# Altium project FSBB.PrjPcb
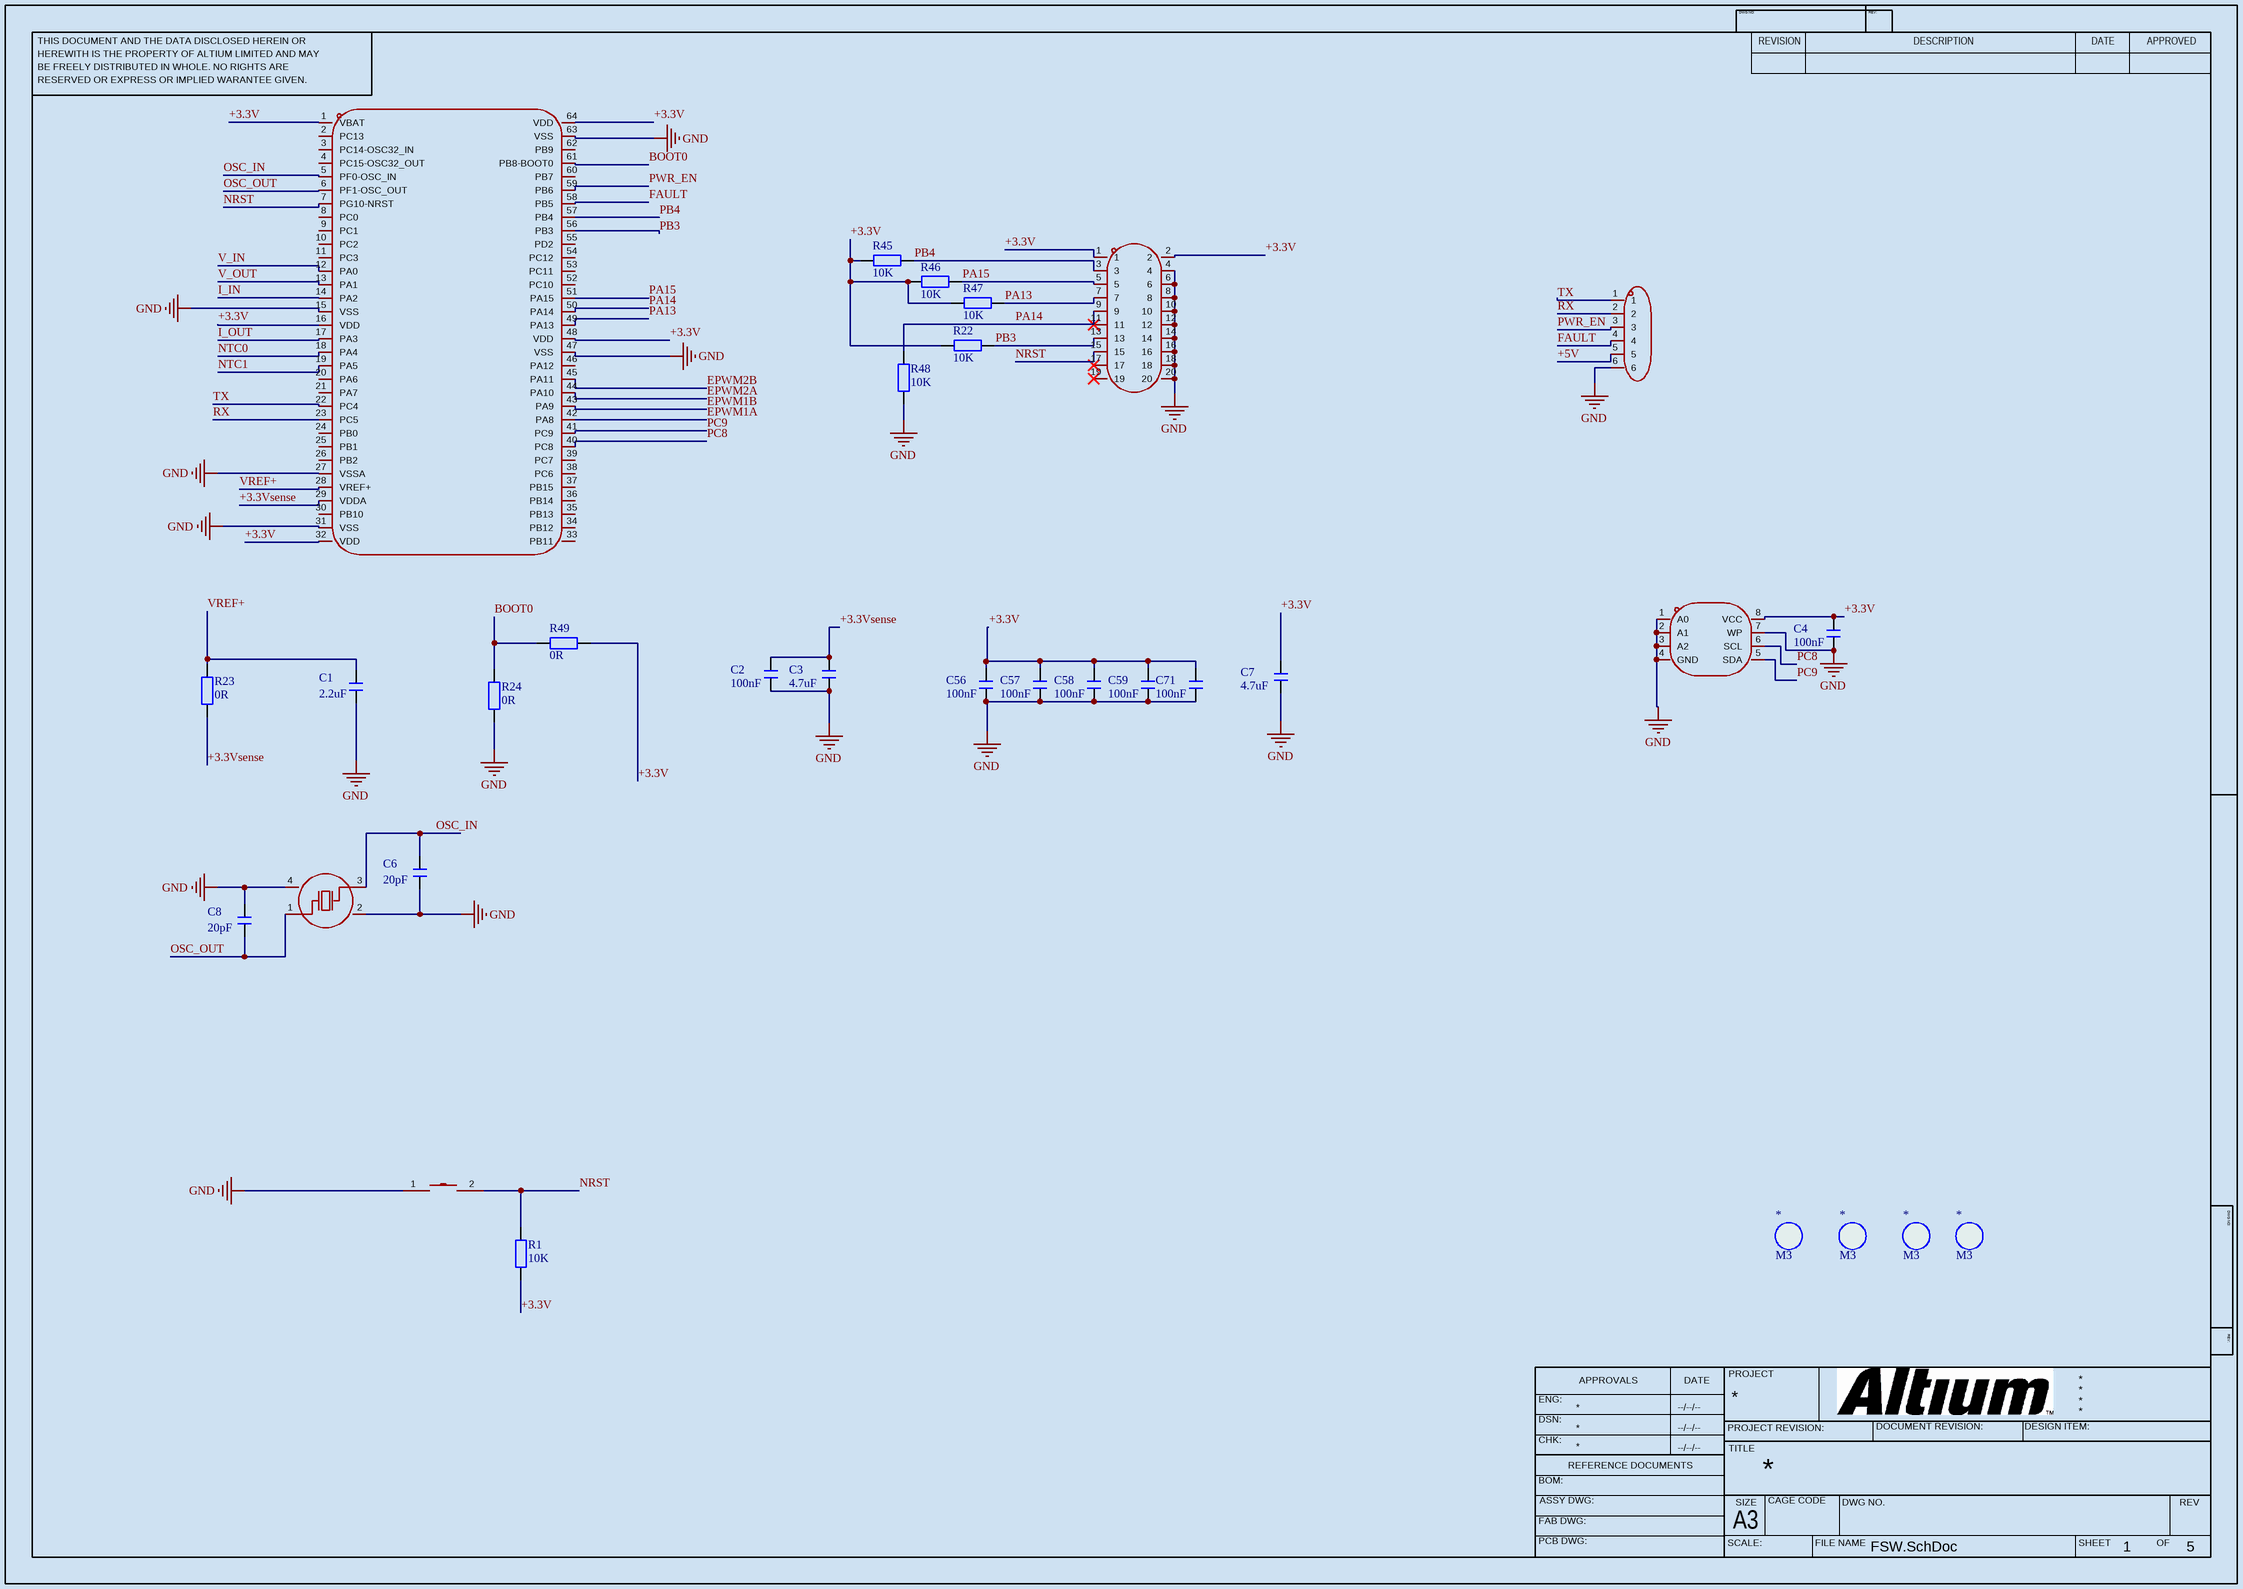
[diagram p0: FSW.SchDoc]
5 sheets, 152 parts. Net scope: global (net labels, ports and power ports of the same name join across sheets).
Board file: FSW.PcbDoc
Sheets:
  FSW.SchDoc
  power.SchDoc
  auxiliary power supply.SchDoc
  sense.SchDoc
  NTC.SchDoc

## Sheet FSW.SchDoc
size 420 x 297 mm; SheetNumber: 1; SheetTotal: 5; ENG_APP_DATE: --/--/--; DSN_APP_DATE: --/--/--; CHK_APP_DATE: --/--/--

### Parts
(Parts that share a designator on the sheet are numbered #1, #2 ... from top to bottom, then left to right.)
*#1  M3  [M3 125X200]
*#2  M3  [M3 125X200]
*#3  M3  [M3 125X200]
*#4  M3  [M3 125X200]
C1  2.2uF  [C 0603_L]
C2  100nF  [C 0603_L]
C3  4.7uF  [C 0603_L]
C4  100nF  [C 0603_L]
C6  20pF  [C 0603_L]
C7  4.7uF  [C 0603_L]
C8  20pF  [C 0603_L]
C56  100nF  [C 0603_L]
C57  100nF  [C 0603_L]
C58  100nF  [C 0603_L]
C59  100nF  [C 0603_L]
C71  100nF  [C 0603_L]
CN1  bh254v-20p  [CONN-TH_20P-P2.54_BH254V-20P]  (value not drawn)
R1  10K  [R 0603_L]
R22  10K  [R 0603_L]
R23  0R  [R 0603_L]
R24  0R  [R 0603_L]
R45  10K  [R 0603_L]
R46  10K  [R 0603_L]
R47  10K  [R 0603_L]
R48  10K  [R 0603_L]
R49  0R  [R 0603_L]
SW1  ts-1101-c-w  [SW-SMD_L6.0-W3.3-LS8.0_TS-1101-C-W]  (value not drawn)
U1  zx-xh2.54-6pzz  [CONN-TH_6P-P2.50_ZX-XH2.54-6PZZ]  (value not drawn)
U14  stm32g474rbt3  [LQFP-64_L10.0-W10.0-P0.50-LS12.0-BL]  (value not drawn)
U15  at24c512c-sshd-t  [SOIC-8_L4.9-W3.9-P1.27-LS6.0-BL]  (value not drawn)
X1  x252024mob4si  [CRYSTAL-SMD_4P-L2.5-W2.0-BL]  (value not drawn)

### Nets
GND: C1.1 C2.1 C3.1 C4.1 C6.1 C7.1 C8.2 C56.1 C57.1 C58.1 C59.1 C71.1 CN1.4 CN1.6 CN1.8 CN1.10 CN1.12 CN1.14 CN1.16 CN1.18 CN1.20 R24.1 R48.2 SW1.1 U1.6 U14.15(VSS) U14.27(VSSA) U14.31(VSS) U14.47(VSS) U14.63(VSS) U15.1(A0) U15.2(A1) U15.3(A2) U15.4(GND) U15.7(WP) X1.2(GND) X1.4(GND)
+3.3V: C4.2 C7.2 C56.2 C57.2 C58.2 C59.2 C71.2 CN1.1 CN1.2 R1.1 R22.2 R45.2 R46.2 R47.2 R49.1 U14.1(VBAT) U14.16(VDD) U14.32(VDD) U14.48(VDD) U14.64(VDD) U15.8(VCC)
+3.3Vsense: C2.2 C3.2 R23.1 U14.29(VDDA)
+5V: U1.5
BOOT0: R24.2 R49.2 U14.61(PB8-BOOT0)
EPWM1A: U14.42(PA8)
EPWM1B: U14.43(PA9)
EPWM2A: U14.44(PA10)
EPWM2B: U14.45(PA11)
FAULT: U1.4 U14.58(PB5)
I_IN: U14.14(PA2)
I_OUT: U14.17(PA3)
NRST: CN1.15 R1.2 SW1.2 U14.7(PG10-NRST)
NTC0: U14.18(PA4)
NTC1: U14.19(PA5)
OSC_IN: C6.2 U14.5(PF0-OSC_IN) X1.3(OSC2)
OSC_OUT: C8.1 U14.6(PF1-OSC_OUT) X1.1(OSC1)
PA13: CN1.7 R47.1 U14.49(PA13)
PA14: CN1.9 CN1.11 R48.1 U14.50(PA14)
PA15: CN1.5 R46.1 U14.51(PA15)
PB3: CN1.13 R22.1 U14.56(PB3)
PB4: CN1.3 R45.1 U14.57(PB4)
PC8: U14.40(PC8) U15.6(SCL)
PC9: U14.41(PC9) U15.5(SDA)
PWR_EN: U1.3 U14.59(PB6)
RX: U1.2 U14.23(PC5)
TX: U1.1 U14.22(PC4)
V_IN: U14.12(PA0)
V_OUT: U14.13(PA1)
VREF+: C1.2 R23.2 U14.28(VREF+)

Not connected (* = marked no-connect by the designer): CN1 17* 19*; U14 2(PC13) 3(PC14-OSC32_IN) 4(PC15-OSC32_OUT) 8(PC0) 9(PC1) 10(PC2) 11(PC3) 20(PA6) 21(PA7) 24(PB0) 25(PB1) 26(PB2) 30(PB10) 33(PB11) 34(PB12) 35(PB13) 36(PB14) 37(PB15) 38(PC6) 39(PC7) 46(PA12) 52(PC10) 53(PC11) 54(PC12) 55(PD2) 60(PB7) 62(PB9)

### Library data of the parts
*#1-*#4 = M3: 铜柱孔; 版权归属: 源创客
C1 C6 C8 = C: 无极性贴片电容; 版权归属: 源创客; 材质: X7R
C2 C4 C56-C59 C71 = C: 6.3V X7R 0603 100nF; BOM名称: 无极性贴片电容; 版权归属: 源创客
C3 C7 = C: 6.3V X7R 0603 4.7uF; BOM名称: 无极性贴片电容; 版权归属: 源创客
CN1 = bh254v-20p: 连接器类型:简牛座;间距:-;结构:2x10P;额定电流:3A;额定电压:250V;安装方式:直插;行距:2.54mm;排数:2;每排PIN数:10;触头材质:-;触头镀层:-;工作温度:-40℃~+105℃;; Manufacturer: XFCN(兴飞); AddInBom: yes; ModelId: f758914ec7d246748ac341cdbdaac489; ModelTransform: 1299.214,350.0906,0,0,0,0,0,1.968,-127.953; Connector Type: 简牛座; Number of Positions or Pins: 2x10P; Current Rating: 3A; Voltage Rating (Max): 250V; Holder Type: 直插; Row Spacing: 2.54mm; Number of PINs Per Row: 10
R1 R22-R24 R45-R49 = R: 贴片电阻; 版权归属: 源创客
SW1 = ts-1101-c-w: 电路结构:单刀单掷;按钮形状:矩形按钮;作用力:2.6N;安装方式:立贴;开关长度:6mm;开关宽度:3.6mm;开关高度:2.5mm;带支架:不带支架;触点电流:50mA;额定电压:12V;带灯:无;工作寿命:5万次;; Manufacturer: XKB Connection(中国星坤); AddInBom: yes; ModelId: 0fd6340cfb7d45bfbbb5f8576d023f85; ModelTransform: 315.232,145.669,0,0,0,0,0,0,0; Circuit: 单刀单掷; Actuator Style: 矩形按钮; Operating Force: 2.6N; Switch Height: 2.5mm; with Bracket: 不带支架; Contact Current: 50mA; Voltage Rating: 12V; With Lamp: 无; Life: 5万次
U1 = zx-xh2.54-6pzz: 插针结构:1x6P;间距:2.5mm;安装方式:直插;参考系列:XH;总PIN数:6P;排数:1;每排PIN数:6;行距:-;额定电流:3A;触头材质:黄铜;触头镀层:锡;工作温度:-25℃~+85℃;; Manufacturer: Megastar(兆星); AddInBom: yes; ModelId: 69bbd5a736b94698bef26e8b4cdae04d; ModelTransform: 688.975,232.6767,0,0,0,0,0,14.528,-133.858; Pins Structure: 1x6P; Pitch: 2.5mm; Reference Series: XH; Number of PINs Per Row: 6; Current Rating: 3A; Voltage Rating: 250V; Plastic Material: PA66; Flame Retardant Rating: UL94V-0; Z-Height of the Board: 7mm; X-Length of Bottom Edge on Board (Spacing Line): 17.5mm; Y-Width of Bottom Edge on Board: 5.9mm
U14 = stm32g474rbt3: CPU内核:ARM Cortex-M4F;CPU最大主频:170MHz;CPU位数:32 Bit;; Manufacturer: ST(意法半导体); AddInBom: yes; ModelId: cd9de06618c44fcf82654c43a457f83c; ModelName: LQFP-64_L10.0-W10.0-H1.4-LS12.0-P0.50; ModelTransform: 472.441,472.441,0,0,0,0,0,0.465,0; CPU Maximum Speed: 170MHz; Core Size: 32 Bit; Program Storage Size: 128KB; Program Memory Type: FLASH; Number of I/O: 52; ADC (Bit): 12bit; Oscillator Type: 内置; Voltage - Supply: 1.71V~3.6V
U15 = at24c512c-sshd-t: 接口类型:I2C;存储容量:512Kbit;时钟频率(fc):1MHz;; Manufacturer: MICROCHIP(美国微芯); AddInBom: yes; ModelId: e81d2f7d937b4a6ab1dca543ff5d56a4; ModelName: SOIC-8_L4.9-W3.9-H1.7-LS6.0-P1.27; ModelTransform: 192.913,236.22,0,0,0,0,0,0,0; Interface: I2C; Clock Frequency: 1MHz; Write Cycle Time(Tw): 5ms; Data Retention - TDR (Year): 40年; Write Cycle Endurance: 100万次; Voltage - Supply: 2.5V~5.5V
X1 = x252024mob4si: 晶振类型:贴片晶振;频率:24MHz;常温频差:±10ppm;负载电容:12pF;频率稳定度:±20ppm;; Manufacturer: YXC(扬兴晶振); AddInBom: yes; ModelId: d23e0abc26e54c15b6292fd5f43702fa; ModelTransform: 98.425,78.74,0,0,0,0,0,0,0; Value: 24MHz; Normal temperature Frequency Tolerance: ±10ppm; Load Capacitance: 12pF; Frequency Stability: ±20ppm; Equivalent Series Resistance(ESR): 100Ω

## Sheet power.SchDoc
size 420 x 297 mm; SheetNumber: 2; SheetTotal: 5; DSN_APP_DATE: --/--/--; CHK_APP_DATE: --/--/--
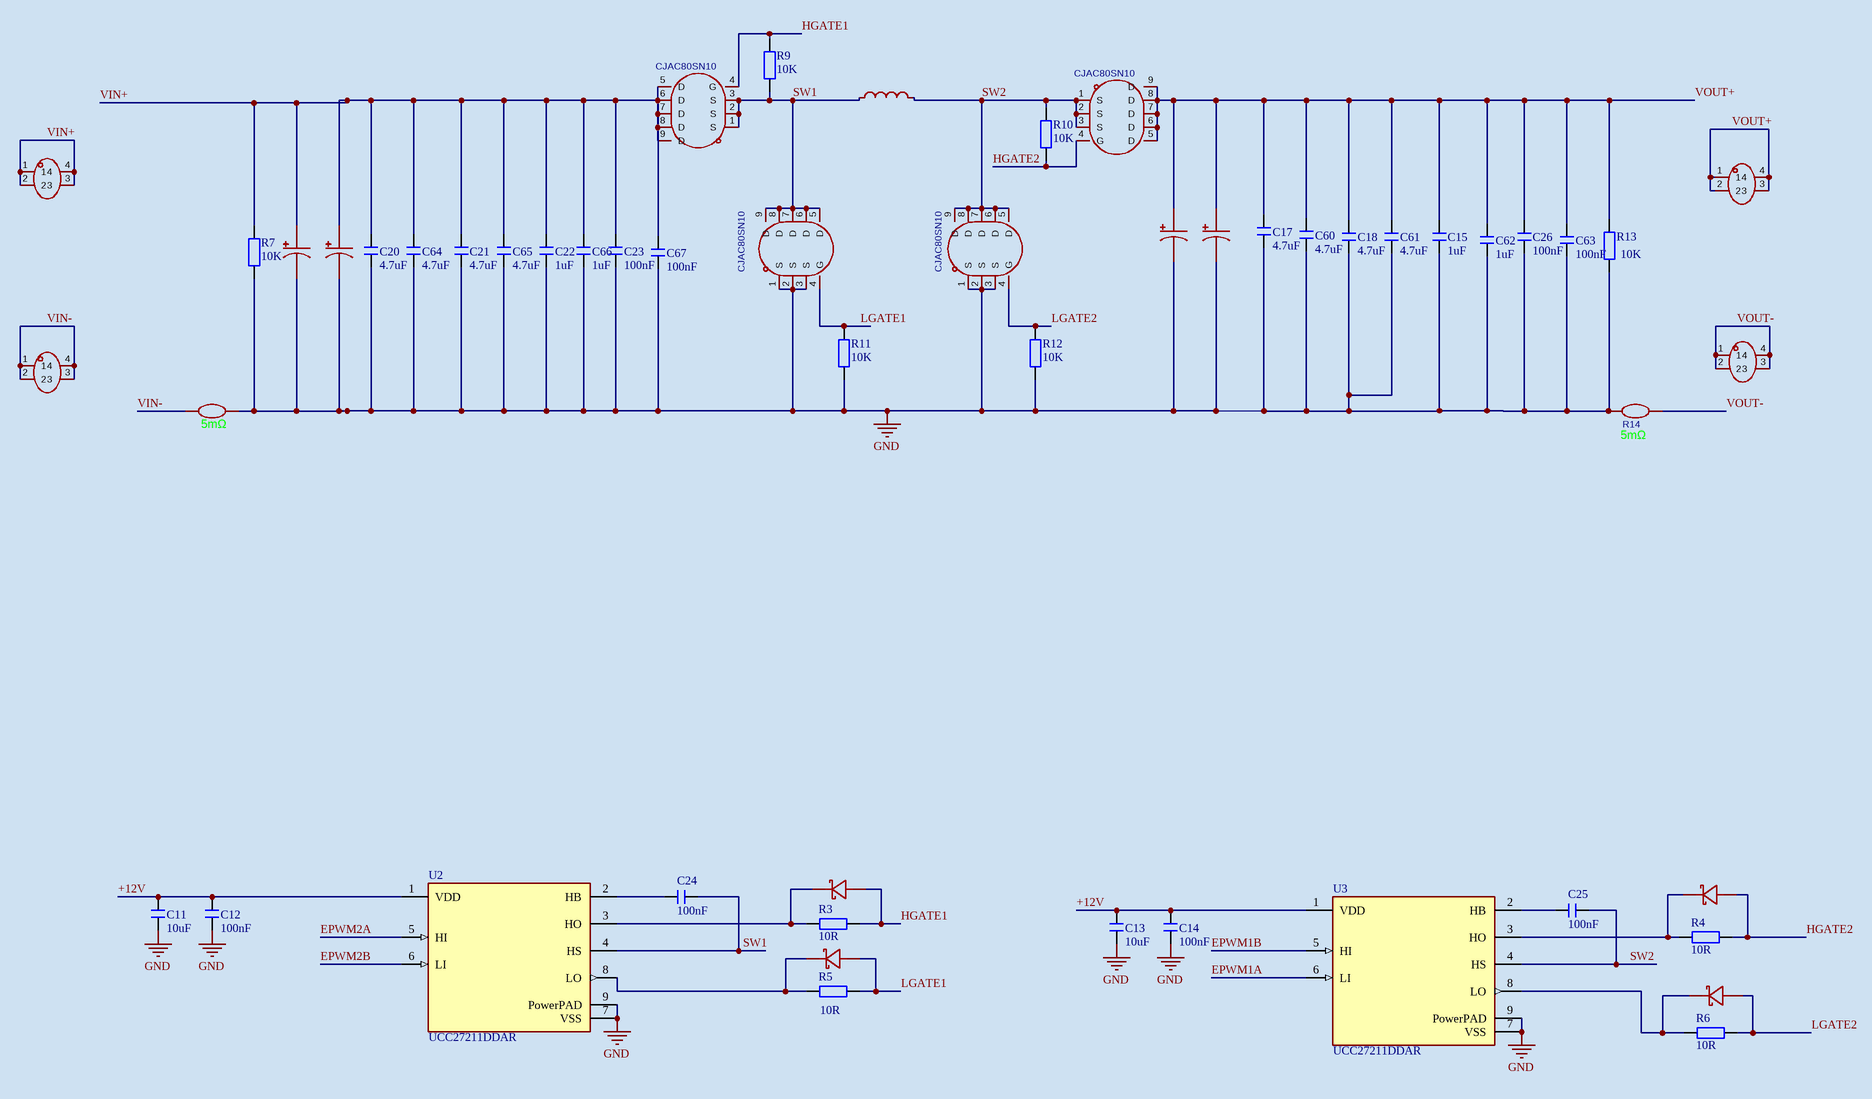
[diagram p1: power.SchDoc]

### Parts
C11  10uF  [C 0805_L]
C12  100nF  [C 0805_L]
C13  10uF  [C 0805_L]
C14  100nF  [C 0805_L]
C15  1uF  [C 1206_L]
C16  100yxj220m12.5x25  [CAP-TH_BD12.5-P5.00-D0.6-FD]  (value not drawn)
C17  4.7uF  [C 1210_L]
C18  4.7uF  [C 1210_L]
C19  100yxj220m12.5x25  [CAP-TH_BD12.5-P5.00-D0.6-FD]  (value not drawn)
C20  4.7uF  [C 1210_L]
C21  4.7uF  [C 1210_L]
C22  1uF  [C 1206_L]
C23  100nF  [C 0805_L]
C24  100nF  [C 0805_L]
C25  100nF  [C 0805_L]
C26  100nF  [C 0805_L]
C53  100yxj220m12.5x25  [CAP-TH_BD12.5-P5.00-D0.6-FD]  (value not drawn)
C54  100yxj220m12.5x25  [CAP-TH_BD12.5-P5.00-D0.6-FD]  (value not drawn)
C60  4.7uF  [C 1210_L]
C61  4.7uF  [C 1210_L]
C62  1uF  [C 1206_L]
C63  100nF  [C 0805_L]
C64  4.7uF  [C 1210_L]
C65  4.7uF  [C 1210_L]
C66  1uF  [C 1206_L]
C67  100nF  [C 0805_L]
D1  1n4148w_c7420318  [SOD-123_L2.7-W1.6-LS3.7-FD]  (value not drawn)
D2  1n4148w_c7420318  [SOD-123_L2.7-W1.6-LS3.7-FD]  (value not drawn)
D3  1n4148w_c7420318  [SOD-123_L2.7-W1.6-LS3.7-FD]  (value not drawn)
D4  1n4148w_c7420318  [SOD-123_L2.7-W1.6-LS3.7-FD]  (value not drawn)
L1  fc-se2822-150m  [IND-TH_L28.0-W23.0_FC-SE2822]  (value not drawn)
Q1  cjac80sn10  [PDFN-8_L5.8-W5.0-P1.27-LS6.0-BL]
Q2  cjac80sn10  [PDFN-8_L5.8-W5.0-P1.27-LS6.0-BL]
Q3  cjac80sn10  [PDFN-8_L5.8-W5.0-P1.27-LS6.0-BL]
Q4  cjac80sn10  [PDFN-8_L5.8-W5.0-P1.27-LS6.0-BL]
R3  10R  [R 0805_L]
R4  10R  [R 0805_L]
R5  10R  [R 0805_L]
R6  10R  [R 0805_L]
R7  10K  [R 1206_L]
R8  value 5mΩ  [RES-SMD_L6.4-W3.2-1]  (hidden comment: hojlr2512-3w-5mr-1%)
R9  10K  [R 0805_L]
R10  10K  [R 0805_L]
R11  10K  [R 0805_L]
R12  10K  [R 0805_L]
R13  10K  [R 1206_L]
R14  value 5mΩ  [RES-SMD_L6.4-W3.2-1]  (hidden comment: hojlr2512-3w-5mr-1%)
U2  UCC27211DDAR  [FP-DDA0008E-IPC_C]
U3  UCC27211DDAR  [FP-DDA0008E-IPC_C]
U10  t34001  [CONN-TH_T34001]  (value not drawn)
U11  t34001  [CONN-TH_T34001]  (value not drawn)
U12  t34001  [CONN-TH_T34001]  (value not drawn)
U13  t34001  [CONN-TH_T34001]  (value not drawn)

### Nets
GND: C11.1 C12.1 C13.1 C14.1 C15.1 C16.2 C17.1 C18.1 C19.2 C20.1 C21.1 C22.1 C23.1 C26.1 C53.2 C54.2 C60.1 C61.1 C62.1 C63.1 C64.1 C65.1 C66.1 C67.1 Q3.1(S) Q3.2(S) Q3.3(S) Q4.1(S) Q4.2(S) Q4.3(S) R7.1 R8.2 R11.1 R12.1 R13.1 R14.1 U2.7(VSS) U2.9(PowerPAD) U3.7(VSS) U3.9(PowerPAD)
+12V: C11.2 C12.2 C13.2 C14.2 U2.1(VDD) U3.1(VDD)
EPWM1A: U3.6(LI)
EPWM1B: U3.5(HI)
EPWM2A: U2.5(HI)
EPWM2B: U2.6(LI)
HGATE1: D1.1(A) Q1.4(G) R3.2 R9.2
HGATE2: D2.1(A) Q2.4(G) R4.2 R10.1
LGATE1: D3.1(A) Q3.4(G) R5.2 R11.2
LGATE2: D4.1(A) Q4.4(G) R6.2 R12.2
SW1: C24.1 L1.1 Q1.1(S) Q1.2(S) Q1.3(S) Q3.5(D) Q3.6(D) Q3.7(D) Q3.8(D) Q3.9(D) R9.1 U2.4(HS)
SW2: C25.1 L1.2 Q2.1(S) Q2.2(S) Q2.3(S) Q4.5(D) Q4.6(D) Q4.7(D) Q4.8(D) Q4.9(D) R10.2 U3.4(HS)
VIN+: C20.2 C21.2 C22.2 C23.2 C53.1 C54.1 C64.2 C65.2 C66.2 C67.2 Q1.5(D) Q1.6(D) Q1.7(D) Q1.8(D) Q1.9(D) R7.2 U10.1 U10.2 U10.3 U10.4
VIN-: R8.1 U13.1 U13.2 U13.3 U13.4
VOUT+: C15.2 C16.1 C17.2 C18.2 C19.1 C26.2 C60.2 C61.2 C62.2 C63.2 Q2.5(D) Q2.6(D) Q2.7(D) Q2.8(D) Q2.9(D) R13.2 U11.1 U11.2 U11.3 U11.4
VOUT-: R14.2 U12.1 U12.2 U12.3 U12.4
NetC24_2: C24.2 U2.2(HB)
NetC25_2: C25.2 U3.2(HB)
NetD1_2: D1.2(K) R3.1 U2.3(HO)
NetD2_2: D2.2(K) R4.1 U3.3(HO)
NetD3_2: D3.2(K) R5.1 U2.8(LO)
NetD4_2: D4.2(K) R6.1 U3.8(LO)

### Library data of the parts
C11 = C: 25V X7R 0805 10uF /; BOM名称: 无极性贴片电容; 版权归属: 源创客
C12 C14 C24 C25 = C: 25V X7R 0805 100nF; BOM名称: 无极性贴片电容; 版权归属: 源创客
C13 = C: 25V X7R 0805 10uF; BOM名称: 无极性贴片电容; 版权归属: 源创客
C15 C62 = C: 100V X7R 1206 1uF; BOM名称: 无极性贴片电容; 版权归属: 源创客
C16 C19 C53 C54 = 100yxj220m12.5x25: 容值:220uF;精度:±20%;额定电压:100V;纹波电流:1.62A@100kHz;等效串联电阻(ESR):-;; Manufacturer: Rubycon(红宝石); AddInBom: yes; ModelId: 968d8ff988964aab8919b46a6a737be2; ModelName: CAP-TH_D12.5-H20.0-P5.00; ModelTransform: 492.5187,492.11201,0,0,0,0,0,0,-137.795; Value: 220uF; Tolerance: ±20%; Voltage Rating: 100V; Pin Spacing: 5mm; Lifetime: 10000hrs@105℃
C17 C18 C60 C61 = C: 100V X7R 1210 4.7uF; BOM名称: 无极性贴片电容; 版权归属: 源创客
C20 C21 C64 C65 = C: 100V X7R 1210  4.7uF; BOM名称: 无极性贴片电容; 版权归属: 源创客
C22 C66 = C: 100V X7R 1206  1uF; BOM名称: 无极性贴片电容; 版权归属: 源创客
C23 = C: 100V X7R 0805 100nF; BOM名称: 无极性贴片电容; 版权归属: 源创客
C26 C63 = C: 100V X7R 0805 100nF /; BOM名称: 无极性贴片电容; 版权归属: 源创客
C67 = C: 100V X7R 0805  100nF /; BOM名称: 无极性贴片电容; 版权归属: 源创客
D1-D4 = 1n4148w_c7420318: 二极管配置:独立式;整流电流:150mA;直流反向耐压(Vr):100V;正向压降(Vf):1.25V@150mA;反向恢复时间(Trr):4ns;; Manufacturer: R+O(宏嘉诚); AddInBom: yes; ModelId: 5054d9b7be8b429dad093a54b517b4dd; ModelTransform: 145.669,61.024,0,0,0,0,0,0,0; Diode Configuration: 独立式; Pd - Power Dissipation: 400mW; Current - Rectified: 150mA; Voltage - DC Reverse(Vr): 100V; Non-Repetitive Peak Forward Surge Current: 2A; Reverse Leakage Current (Ir): 1uA@75V; Reverse Recovery Time (trr): 4ns; Operating Junction Temperature Range: -55℃~+150℃
L1 = fc-se2822-150m: 电感值:15uH;精度:±20%;额定电流:30A;饱和电流(Isat):30.5A;类型:-;; Manufacturer: FC(方成); AddInBom: yes; ModelId: b1b8f7090fd941118d4b89044bfce1b2; ModelTransform: 1102.36,905.51,0,0,0,0,0,0,-137.795; Value: 15uH; Tolerance: ±20%; Current Rating: 30A; Current - Saturation(Isat): 30.5A; DC Resistance(DCR): 3.5mΩ
Q1-Q4 = cjac80sn10: 数量:1个N沟道;漏源电压(Vdss):100V;连续漏极电流(Id):80A;导通电阻(RDS(on)):10.5mΩ@4.5V;耗散功率(Pd):100W;阈值电压(Vgs(th)):2.5V;; Manufacturer: CJ(江苏长电/长晶); AddInBom: yes; ModelId: 64dd0a0ad16f4146a485008a6fd3b168; ModelTransform: 193.7004,238.189,0,0,0,0,0,0,0; Number: 1个N沟道; Drain to Source Voltage: 100V; Current - Continuous Drain(Id): 80A; Pd - Power Dissipation: 100W; Gate Threshold Voltage (Vgs(th)): 2.5V; Gate Charge(Qg): 100nC@10V; Input Capacitance(Ciss): 3.15nF; Reverse Transfer Capacitance (Crss@Vds): 8pF; Type: N沟道; Output Capacitance(Coss): 650pF
R3-R7 R9-R13 = R: 贴片电阻; 版权归属: 源创客
R8 R14 = hojlr2512-3w-5mr-1%: 电阻类型:采样电阻;阻值:5mΩ;精度:±1%;功率:3W;安装方式:贴片;; Manufacturer: Milliohm(毫欧); AddInBom: yes; ModelId: 2a92684014bd46c593e4aa7ce823c350; ModelTransform: 251.968,125.984,0,0,0,0,0,0,0; Tolerance: ±1%; Power(Watts): 3W; Mounting Sytle: 贴片
U2 U3 = CMP-04912-000066-1: IC GATE DRVR HALF-BRIDGE 8SOPWR; Supply Current: 4A; Number of Channels: 2; Turn-On Delay Time: 40ns; Max Output Current: 4.5A; Max Supply Voltage: 17V; Max Supply Current: 4.3mA; Fall Time: 400ns; Min Supply Voltage: 8V; Operating Supply Voltage: 12V; Rise Time: 600ns
U10-U13 = t34001: Manufacturer: XFCN(兴飞); AddInBom: yes; ModelId: 9a18b4251ffd4ebd840028391c6881d2; ModelTransform: 314.96,314.96,0,0,0,0,0,0,-118.11

## Sheet auxiliary power supply.SchDoc
size A4; SheetNumber: 3; SheetTotal: 5
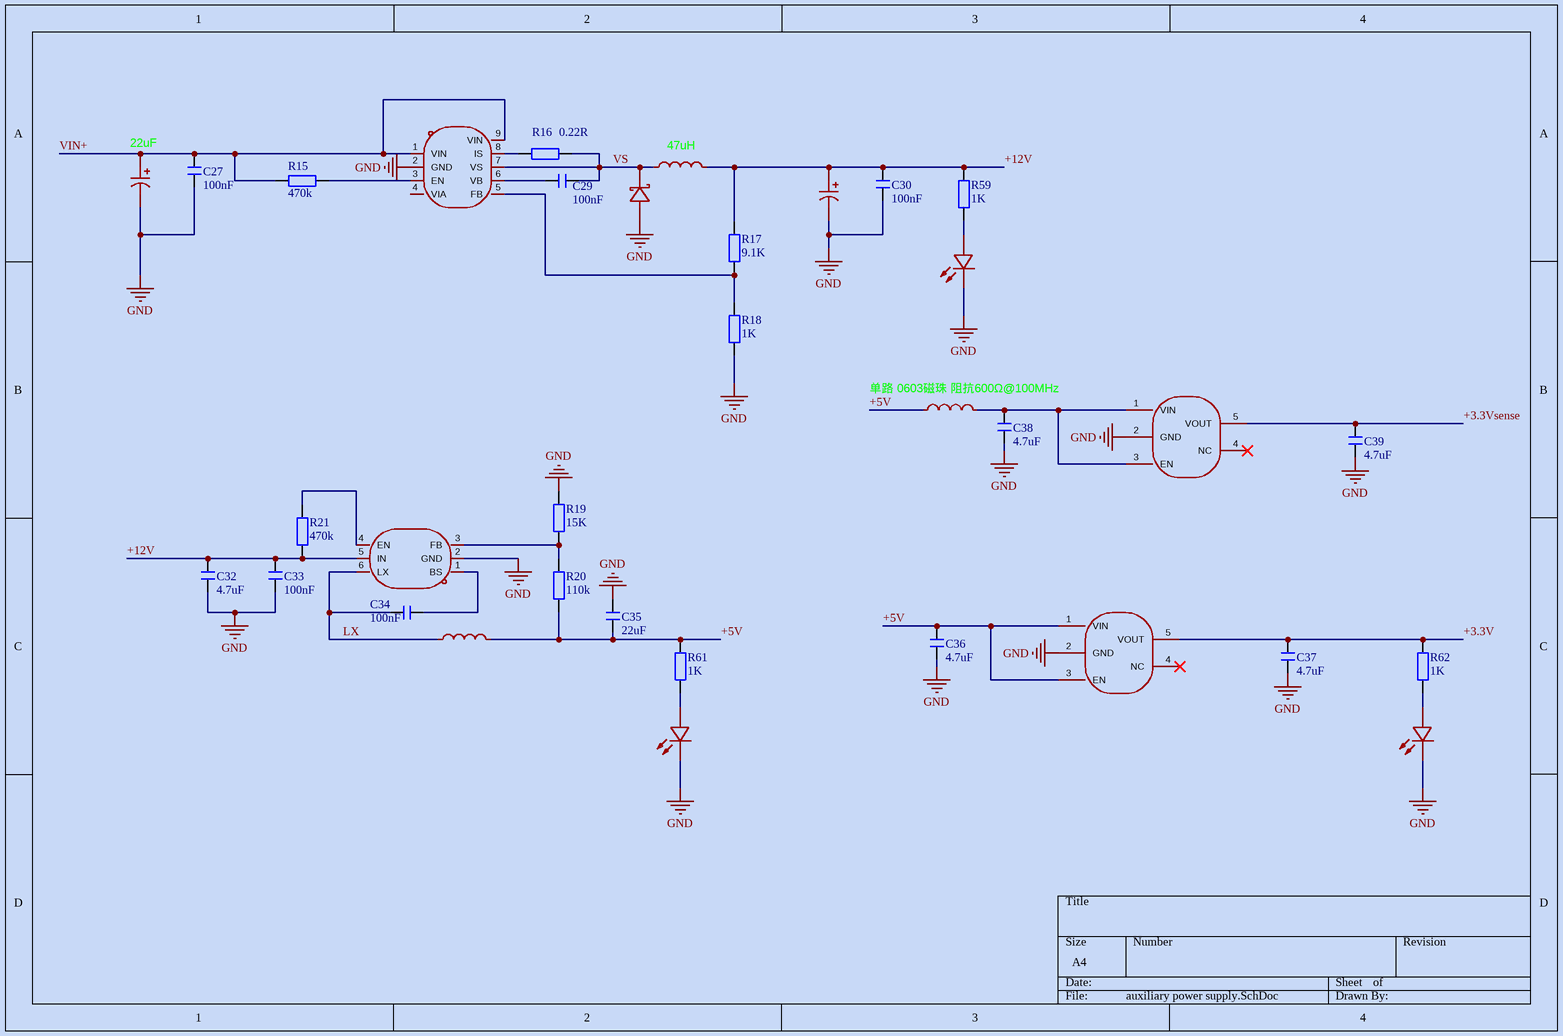
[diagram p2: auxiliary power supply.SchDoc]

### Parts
C27  100nF  [C 0805_L]
C28  value 22uF  [CAP-SMD_BD6.3-L6.6-W6.6-LS7.3-FD-H7.7]  (hidden comment: jvj100v22m6x8)
C29  100nF  [C 0603_L]
C30  100nF  [C 0805_L]
C31  ma25v220m6x8  [CAP-SMD_BD6.3-L6.6-W6.6-LS7.3-FD]  (value not drawn)
C32  4.7uF  [C 0805_L]
C33  100nF  [C 0805_L]
C34  100nF  [C 0805_L]
C35  22uF  [C 0805_L]
C36  4.7uF  [C 0805_L]
C37  4.7uF  [C 0805_L]
C38  4.7uF  [C 0805_L]
C39  4.7uF  [C 0805_L]
D5  ss310_c7420364  [SMA_L4.3-W2.6-LS5.0-FD]  (value not drawn)
L2  value 47uH  [IND-SMD_L7.0-W6.6_FXL0630]  (hidden comment: fxl0630-470-m)
L3  ftc252010s4r7mbca  [IND-SMD_L2.5-W2.0-VLS252012CX-150M]  (value not drawn)
L4  LCSC Part Name: 单路 0603磁珠 阻抗600Ω@100MHz  [L0603]  (hidden comment: gz1608d601tf)
LED1  ncd0805r1  [LED0805-RD]  (value not drawn)
LED3  ncd0805r1  [LED0805-RD]  (value not drawn)
LED4  ncd0805r1  [LED0805-RD]  (value not drawn)
R15  470k  [R 0805_L]
R16  0.22R  [R 1206_L]
R17  9.1K  [R 0805_L]
R18  1K  [R 0805_L]
R19  15K  [R 0805_L]
R20  110k  [R 0805_L]
R21  470k  [R 0805_L]
R59  1K  [R 0805_L]
R61  1K  [R 0805_L]
R62  1K  [R 0805_L]
U4  eg1192l  [ESOP-8_L4.9-W3.9-P1.27-LS6.0-BL-EP]  (value not drawn)
U5  sy8120b1abc  [SOT-23-6_L2.9-W1.6-P0.95-LS2.8-BL]  (value not drawn)
U6  rt9013-33gb  [SOT-23-5_L3.0-W1.7-P0.95-LS2.8-BL]  (value not drawn)
U7  rt9013-33gb  [SOT-23-5_L3.0-W1.7-P0.95-LS2.8-BL]  (value not drawn)

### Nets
GND: C27.1 C28.2 C30.1 C31.2 C32.1 C33.1 C35.2 C36.1 C37.1 C38.1 C39.1 D5.1(A) LED1.1(-) LED3.1(-) LED4.1(-) R18.1 R19.2 U4.2(GND) U5.2(GND) U6.2(GND) U7.2(GND)
+3.3V: C37.2 R62.2 U6.5(VOUT)
+3.3Vsense: C39.2 U7.5(VOUT)
+5V: C35.1 C36.2 L3.2 L4.1 R20.1 R61.2 U6.1(VIN) U6.3(EN)
+12V: C30.2 C31.1 C32.2 C33.2 L2.2 R17.2 R21.1 R59.2 U5.5(IN)
LX: C34.1 L3.1 U5.6(LX)
VIN+: C27.2 C28.1 R15.1 U4.1(VIN) U4.9(VIN)
VS: C29.2 D5.2(K) L2.1 R16.2 U4.7(VS)
NetC29_1: C29.1 U4.6(VB)
NetC34_2: C34.2 U5.1(BS)
NetC38_2: C38.2 L4.2 U7.1(VIN) U7.3(EN)
NetLED1_2: LED1.2(+) R59.1
NetLED3_2: LED3.2(+) R61.1
NetLED4_2: LED4.2(+) R62.1
NetR15_2: R15.2 U4.3(EN)
NetR16_1: R16.1 U4.8(IS)
NetR17_1: R17.1 R18.2 U4.5(FB)
NetR19_1: R19.1 R20.2 U5.3(FB)
NetR21_2: R21.2 U5.4(EN)

Not connected (* = marked no-connect by the designer): U4 4(VIA); U6 4(NC)*; U7 4(NC)*

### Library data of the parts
C27 = C: as C23 on sheet power
C28 = jvj100v22m6x8: 容值:22uF;精度:±20%;额定电压:100V;纹波电流:60mA@120Hz;; Manufacturer: JIERR(捷而瑞); AddInBom: yes; ModelId: ccbda52dceed4b139172c40f75c9da3f; ModelTransform: 287.401,259.842,0,0,0,0,0,0,0; Tolerance: ±20%; Voltage Rating: 100V; Lifetime: 2000hrs@105℃
C29 C30 C33 C34 = C: as C12 on sheet power
C31 = ma25v220m6x8: 容值:220uF;精度:±20%;额定电压:25V;纹波电流:2.9A@100kHz;等效串联电阻(ESR):28mΩ@100kHz;类型:聚合物;; Manufacturer: JIERR(捷而瑞); AddInBom: yes; ModelId: 697a8c63e3274188b68c96045bc3ea1c; ModelTransform: 287.401,259.842,0,180,0,0,0.001,0.001,0; Value: 220uF; Tolerance: ±20%; Voltage Rating: 25V; Type: 聚合物; Lifetime: 2000hrs@105℃
C32 = C: 25V X7R 0805 4.7uF; BOM名称: 无极性贴片电容; 版权归属: 源创客
C35 = C: 16V X7R 0805 22uF; BOM名称: 无极性贴片电容; 版权归属: 源创客
C36 C37 C39 = C: 16V X7R 0805 4.7uF; BOM名称: 无极性贴片电容; 版权归属: 源创客
C38 = C: 16V X7R 0805 4.7uF /; BOM名称: 无极性贴片电容; 版权归属: 源创客
D5 = ss310_c7420364: 二极管配置:独立式;正向压降(Vf):850mV@3A;直流反向耐压(Vr):100V;整流电流:3A;; Manufacturer: R+O(宏嘉诚); ManufacturerPart: SS310; AddInBom: yes; ModelId: 7e24bebe6cd74171ae8c9de6fc5b78aa; ModelTransform: 198.4248,103.5431,0,180,0,0,-0.001,0,0; Diode Configuration: 独立式; Voltage - DC Reverse(Vr): 100V; Current - Rectified: 3A; Reverse Leakage Current (Ir): 50uA@100V; Operating Junction Temperature Range: -55℃~+150℃; Non-Repetitive Peak Forward Surge Current: 80A
L2 = fxl0630-470-m: 电感值:47uH;精度:±20%;额定电流:1.5A;饱和电流(Isat):2A;类型:一体成型电感;; Manufacturer: cjiang(长江微电); AddInBom: yes; ModelId: 6712504104d74f0ca01cd7d0df9965b7; ModelName: IND-SMD_L7.0-W6.6-H2.8_FXL0630; ModelTransform: 275.59,259.842,0,0,0,0,0,0,0; Tolerance: ±20%; Rated Current: 1.5A; Saturation Current (Isat): 2A; DC Resistance (DCR): 385mΩ; Type: 一体成型电感
L3 = ftc252010s4r7mbca: 电感值:4.7uH;精度:±20%;额定电流:2A;饱和电流(Isat):2.6A;类型:-;; Manufacturer: cjiang(长江微电); AddInBom: yes; ModelId: e143e04106934774881cec608355723f; ModelTransform: 98.504,78.819,0,0,0,0,-0.004,-0.003,0; Value: 4.7uH; Tolerance: ±20%; Current Rating: 2A; Current - Saturation(Isat): 2.6A; DC Resistance(DCR): 160mΩ
L4 = gz1608d601tf: 阻抗@频率:600Ω@100MHz;误差:±25%;直流电阻(DCR):450mΩ;; Manufacturer: Sunlord(顺络); AddInBom: yes; ModelId: 2bc5ec593d464d6ba9807aec0b5673c2; ModelName: L0603_L1.6-W0.8-H0.5_BEAD; ModelTransform: 62.992,31.496,0,180,0,0,0.094,0.629,0; Tolerance: ±25%; DC Resistance(DCR): 450mΩ; Current Rating: 200mA; Number of Circuits: 1
LED1 LED3 LED4 = ncd0805r1: 灯头类型:-;发光颜色:红色;正向压降(Vf):1.6V~2.6V;功率:65mW;正向电流:25mA;波长:615nm~630nm;二极管配置:独立二极管;透镜颜色:-;色温:-;发光强度:195mcd;发光角度:130°;载带方式:-;工作温度:-30℃~+85℃;; Manufacturer: 国星光电; Symbol: FC-2012HRK-620D; AddInBom: yes; ModelId: b1c5ed7a4f6e46d3bc6f6cc7c20f3fea; ModelTransform: 79.527,49.2125,0,0,0,0,0,0,0; Illumination Color: 红色; Power(Watts): 65mW; Forward Current: 25mA; Peak Wavelength: 630nm; Diode Configuration: 独立二极管; Luminous Intensity: 195mcd; Viewing Angle: 130°
R15-R21 R59 R61 R62 = R: 贴片电阻; 版权归属: 源创客
U4 = eg1192l: 功能类型:降压型;工作电压:10V~100V;输出电压:-;输出电流:3A;输出类型:可调;; Manufacturer: EG(屹晶微); AddInBom: yes; ModelId: d3e00daa36c445139c055a3b9efb85d2; ModelName: ESOP-8_L4.9-W3.9-H1.6-LS6.0-P1.27; ModelTransform: 240.157,192.913,0,90,0,0,0,0,0; Function: 降压型; Output Current: 3A; Frequency - Switching: 110kHz; Synchronous Rectifier: 否; Number of Outputs: 1; Topology: 降压式; Quiescent Current: 2mA; Switch tube (built-in/external): 内置; Output Type: 可调
U5 = sy8120b1abc: 功能类型:降压型;工作电压:4.5V~18V;输出电压:-;输出电流:2A;输出类型:可调;; Manufacturer: Silergy(矽力杰); AddInBom: yes; ModelId: 18da8f6c14a34920b3e136b5c401a119; ModelName: SOT-23-6_L2.9-W1.6-H1.5-LS2.8-P0.95; ModelTransform: 110.236,113.364,0,90,0,0,0.0005,0.0005,0; Function: 降压型; Output Current: 2A; Frequency - Switching: 500kHz; Synchronous Rectifier: 是; Number of Outputs: 1; Topology: 降压式; Quiescent Current: 400uA; Switch tube (built-in/external): 内置; Output Type: 可调
U6 U7 = rt9013-33gb: 输出极性:正极;工作电压:5.5V;输出电压:3.3V;输出电流:500mA;电源纹波抑制比(PSRR):50dB@(10kHz);输出类型:固定;; Manufacturer: RICHTEK(立锜); AddInBom: yes; ModelId: 0a2a1b8f50944f73965918ad6e5fe167; ModelName: SOT-23-5_L2.9-W1.6-H1.1-LS2.8-P0.95; ModelTransform: 118.60433,114.173,0,90,0,0,0.0005,0.0005,0; Output Configuration: 正极; Voltage - Supply: 5.5V; Output Voltage: 3.3V; Output Current: 500mA; Voltage Dropout: 400mV@(500mA); standby current: 25uA; Noise: 30uVrms; Output Type: 固定; Number of Outputs: 1

## Sheet sense.SchDoc
size A4; SheetNumber: 4; SheetTotal: 5
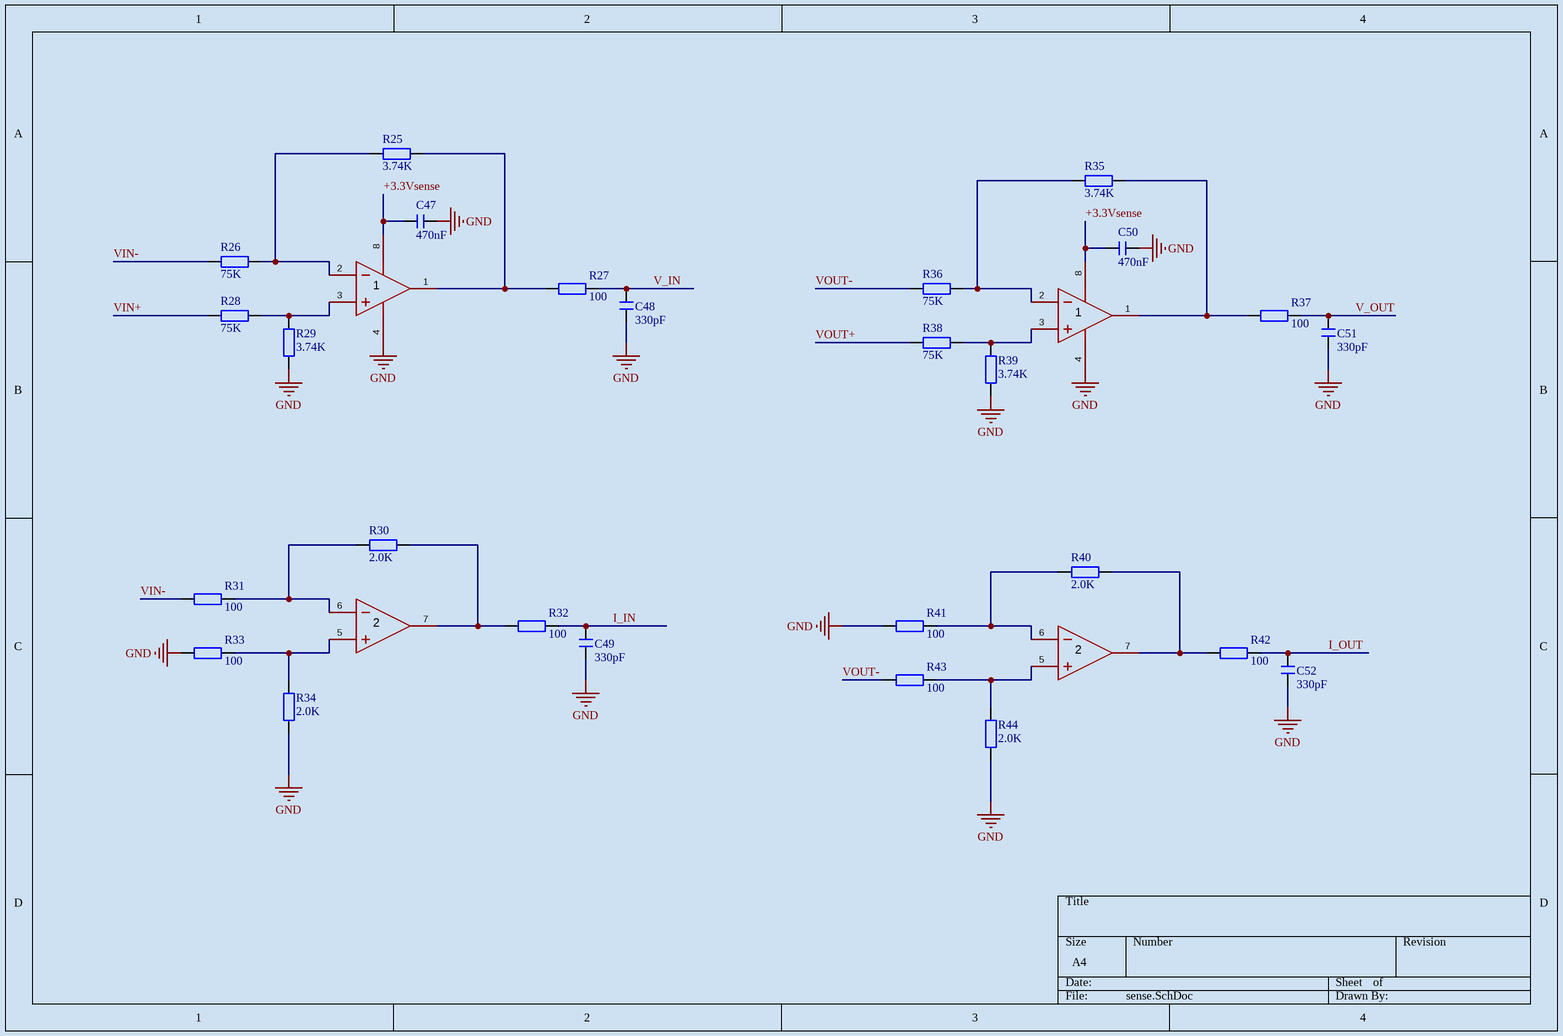
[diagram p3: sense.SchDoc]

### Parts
C47  470nF  [C 0603_L]
C48  330pF  [C 0603_L]
C49  330pF  [C 0603_L]
C50  470nF  [C 0603_L]
C51  330pF  [C 0603_L]
C52  330pF  [C 0603_L]
R25  3.74K  [R 0603_L]
R26  75K  [R 0805_L]
R27  100  [R 0603_L]
R28  75K  [R 0805_L]
R29  3.74K  [R 0603_L]
R30  2.0K  [R 0603_L]
R31  100  [R 0603_L]
R32  100  [R 0603_L]
R33  100  [R 0603_L]
R34  2.0K  [R 0603_L]
R35  3.74K  [R 0603_L]
R36  75K  [R 0805_L]
R37  100  [R 0603_L]
R38  75K  [R 0805_L]
R39  3.74K  [R 0603_L]
R40  2.0K  [R 0603_L]
R41  100  [R 0603_L]
R42  100  [R 0603_L]
R43  100  [R 0603_L]
R44  2.0K  [R 0603_L]
U8  gs8558-sr  [SOIC-8_L4.9-W3.8-P1.27-LS6.0-BL]  (value not drawn)  (parts A,B of 2)
U9  gs8558-sr  [SOIC-8_L4.9-W3.8-P1.27-LS6.0-BL]  (value not drawn)  (parts A,B of 2)

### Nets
GND: C47.2 C48.1 C49.1 C50.2 C51.1 C52.1 R29.1 R33.1 R34.1 R39.1 R41.1 R44.1 U8.4(VSS) U9.4(VSS)
+3.3Vsense: C47.1 C50.1 U8.8(VDD) U9.8(VDD)
I_IN: C49.2 R32.2
I_OUT: C52.2 R42.2
V_IN: C48.2 R27.2
V_OUT: C51.2 R37.2
VIN+: R28.1
VIN-: R26.1 R31.1
VOUT+: R38.1
VOUT-: R36.1 R43.1
NetR25_1: R25.1 R27.1 U8.1(OUTA)
NetR25_2: R25.2 R26.2 U8.2(-INA)
NetR28_2: R28.2 R29.2 U8.3(+INA)
NetR30_1: R30.1 R32.1 U8.7(OUTB)
NetR30_2: R30.2 R31.2 U8.6(-INB)
NetR33_2: R33.2 R34.2 U8.5(+INB)
NetR35_1: R35.1 R37.1 U9.1(OUTA)
NetR35_2: R35.2 R36.2 U9.2(-INA)
NetR38_2: R38.2 R39.2 U9.3(+INA)
NetR40_1: R40.1 R42.1 U9.7(OUTB)
NetR40_2: R40.2 R41.2 U9.6(-INB)
NetR43_2: R43.2 R44.2 U9.5(+INB)

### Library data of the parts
C47 C50 = C: 6.3V X7R 0603 470nF; BOM名称: 无极性贴片电容; 版权归属: 源创客
C48 C51 C52 = C: 6.3V X7R 0603 330pF; BOM名称: 无极性贴片电容; 版权归属: 源创客
C49 = C: 无极性贴片电容; 版权归属: 源创客; 材质: X7R
R25-R44 = R: 贴片电阻; 版权归属: 源创客
U8 U9 = gs8558-sr: 放大器数:双路;增益带宽积(GBP):13MHz;输入偏置电流(Ib):100pA;输入失调电压(Vos):5uV;压摆率(SR):8V/us;轨到轨:轨到轨输入,轨到轨输出;; Manufacturer: Gainsil(聚洵); AddInBom: yes; ModelId: ca0cccb852be401a81142c6d2d7c8054; ModelTransform: 192.913,236.22,0,0,0,0,-0.002,0,0; Number of Channels: 双路; Gain Bandwidth Product: 13MHz; Ib - Input Bias Current: 100pA; Vos - Input Offset Voltage: 5uV; Common Mode Rejection Ratio(CMRR): 100dB; Slew Rate: 8V/us; Output Current: 109mA; Input Offset Voltage Drift(Vos TC): 27nV/℃; Quiescent Current(Iq): 1.3mA; Single Supply: 2.5V~5.5V; Dual Supply: 1.25V~2.75V；-2.75V~-1.25V; Maximum Power Supply Range (Vdd-Vss): 5.5V; Input Offset Current(Ios): 10pA

## Sheet NTC.SchDoc
size A4; SheetNumber: 5; SheetTotal: 5
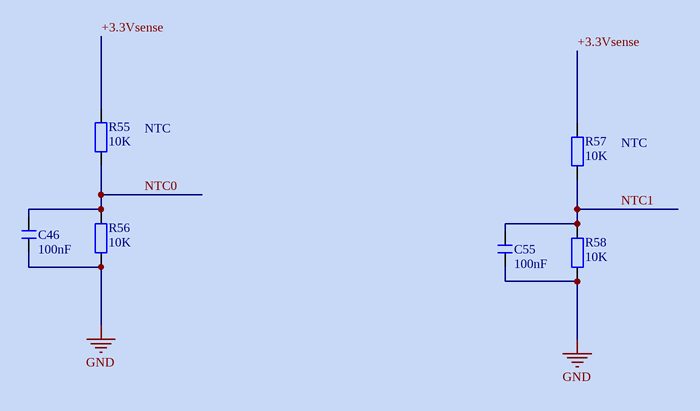
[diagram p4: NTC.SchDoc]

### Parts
C46  100nF  [C 0603_L]
C55  100nF  [C 0603_L]
R55  10K  [R 0603_L]
R56  10K  [R 0603_L]
R57  10K  [R 0603_L]
R58  10K  [R 0603_L]

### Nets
GND: C46.1 C55.1 R56.1 R58.1
+3.3Vsense: R55.2 R57.2
NTC0: C46.2 R55.1 R56.2
NTC1: C55.2 R57.1 R58.2

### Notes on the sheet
- (near R55) NTC
- (near R57) NTC

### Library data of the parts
C46 C55 = C: 无极性贴片电容; 版权归属: 源创客; 材质: X7R
R55 R57 = R: 贴片电阻NTC; BOM名称: 贴片电阻; 版权归属: 源创客
R56 R58 = R: 贴片电阻; 版权归属: 源创客

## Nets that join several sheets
GND: FSW (37 pins), power (40 pins), auxiliary power supply (21 pins), sense (14 pins), NTC (C46.1 C55.1 R56.1 R58.1)
+3.3V: FSW (21 pins), auxiliary power supply (C37.2 R62.2 U6.5)
+3.3Vsense: FSW (C2.2 C3.2 R23.1 U14.29), auxiliary power supply (C39.2 U7.5), sense (C47.1 C50.1 U8.8 U9.8), NTC (R55.2 R57.2)
+5V: FSW (U1.5), auxiliary power supply (8 pins)
+12V: power (6 pins), auxiliary power supply (9 pins)
EPWM1A: FSW (U14.42), power (U3.6)
EPWM1B: FSW (U14.43), power (U3.5)
EPWM2A: FSW (U14.44), power (U2.5)
EPWM2B: FSW (U14.45), power (U2.6)
I_IN: FSW (U14.14), sense (C49.2 R32.2)
I_OUT: FSW (U14.17), sense (C52.2 R42.2)
NTC0: FSW (U14.18), NTC (C46.2 R55.1 R56.2)
NTC1: FSW (U14.19), NTC (C55.2 R57.1 R58.2)
V_IN: FSW (U14.12), sense (C48.2 R27.2)
V_OUT: FSW (U14.13), sense (C51.2 R37.2)
VIN+: power (20 pins), auxiliary power supply (5 pins), sense (R28.1)
VIN-: power (5 pins), sense (R26.1 R31.1)
VOUT+: power (20 pins), sense (R38.1)
VOUT-: power (5 pins), sense (R36.1 R43.1)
